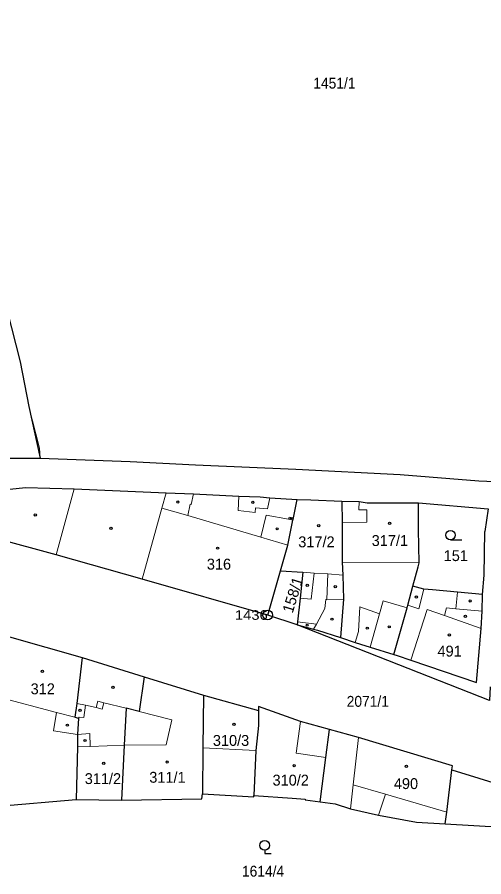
# Model space of a CAD drawing. Extents: x -679733 to -673243, y -1075091 to -1066557.
# Drawn here: x -676925.4 to -676852.3, y -1071438.3 to -1071303.8 of the extents above; entities that cross this region are included whole.
import ezdxf
from ezdxf.enums import TextEntityAlignment as Align

# ---------------------------------------------------------------- set-up
doc = ezdxf.new("R2010")
doc.units = 0
doc.header["$LTSCALE"] = 0.68
for name, color, linetype, lineweight in [('1', 7, 'Continuous', 25), ('3', 7, 'Continuous', 25), ('4', 7, 'Continuous', 13), ('5', 7, 'Continuous', 25), ('8', 7, 'Continuous', 25)]:
    doc.layers.add(name, color=color, linetype=linetype, lineweight=lineweight)
doc.layers.add('2', color=7, linetype='Continuous')

msp = doc.modelspace()

# ---------------------------------------------------------------- linework, layer by layer
at = {"layer": '1'}
for p, q in [((-676886.15, -1071397.33), (-676884.15, -1071390.4)), ((-676896.18, -1071409.85), (-676887.58, -1071412.26)), ((-676916.15, -1071426.2), (-676909.02, -1071426.28))]:
    msp.add_line(p, q, dxfattribs=at)
for points in [[(-676940.16, -1071295.32), (-676934.27, -1071320.03), (-676929.64, -1071339.29), (-676924.89, -1071357.71), (-676923.53, -1071364.72), (-676921.77, -1071372.81)], [(-676946.6, -1071378.41), (-676938.25, -1071374.31), (-676936.51, -1071373.51), (-676931.26, -1071373.06), (-676927.41, -1071372.78), (-676921.77, -1071372.81)], [(-676921.77, -1071372.81), (-676907.7, -1071373.32), (-676897.48, -1071373.81), (-676881.76, -1071374.51), (-676865.44, -1071375.36), (-676853.12, -1071376.35), (-676839.6, -1071376.93), (-676829.31, -1071377.63), (-676824, -1071376.8), (-676807.89, -1071372.89), (-676806.71, -1071372.6)], [(-676926.52, -1071377.66), (-676924.04, -1071377.38), (-676916.45, -1071377.59), (-676902.06, -1071378.22), (-676897.79, -1071378.38), (-676890.67, -1071378.71), (-676887.35, -1071378.83), (-676885.82, -1071378.98), (-676881.52, -1071379.23)], [(-676884.15, -1071390.4), (-676882.99, -1071386.38), (-676882.2, -1071382.48), (-676882.13, -1071382.14), (-676881.52, -1071379.23)], [(-676881.52, -1071379.23), (-676879.42, -1071379.29), (-676874.54, -1071379.53)], [(-676874.54, -1071379.53), (-676874.52, -1071382.83), (-676874.49, -1071389.08), (-676874.37, -1071391.08), (-676874.28, -1071394.86), (-676874.78, -1071400.87)], [(-676874.54, -1071379.53), (-676871.83, -1071379.59), (-676870.57, -1071379.75), (-676862.57, -1071379.75)], [(-676863.46, -1071392.84), (-676862.62, -1071389.77), (-676862.43, -1071389.14), (-676862.53, -1071383.97), (-676862.57, -1071379.75)], [(-676862.57, -1071379.75), (-676851.64, -1071380.72), (-676852.15, -1071384.24)], [(-676886.15, -1071397.33), (-676905.82, -1071391.71), (-676919.25, -1071387.91), (-676928.69, -1071385.35), (-676934.93, -1071383.52)], [(-676852.51, -1071394.1), (-676852.27, -1071391.08), (-676852.15, -1071384.24)], [(-676884.15, -1071390.4), (-676880.65, -1071390.64), (-676881.08, -1071394.68), (-676881.48, -1071398.39), (-676881.53, -1071398.84)], [(-676866.42, -1071403.52), (-676864.34, -1071396.21), (-676864.22, -1071395.79), (-676863.46, -1071392.84)], [(-676852.51, -1071394.1), (-676856.44, -1071393.75), (-676860.36, -1071393.37), (-676861.71, -1071393.27), (-676863.46, -1071392.84)], [(-676949.74, -1071393.86), (-676947.08, -1071394.44), (-676942.33, -1071395.72), (-676930.37, -1071399.53), (-676926.55, -1071400.72), (-676915.2, -1071403.96), (-676905.51, -1071407), (-676896.18, -1071409.85)], [(-676866.42, -1071403.52), (-676865.9, -1071403.66), (-676863.75, -1071404.41), (-676853.5, -1071407.89), (-676852.74, -1071399.45), (-676852.59, -1071396.73), (-676852.51, -1071394.1)], [(-676851.36, -1071408.59), (-676851.44, -1071410.69), (-676881.53, -1071398.84), (-676886.15, -1071397.33)], [(-676881.53, -1071398.84), (-676878.97, -1071399.54), (-676878.36, -1071399.71), (-676874.78, -1071400.87)], [(-676874.78, -1071400.87), (-676872.44, -1071401.63), (-676871.65, -1071401.89), (-676870.12, -1071402.35), (-676866.42, -1071403.52)], [(-676915.2, -1071403.96), (-676916.03, -1071411.16), (-676916.33, -1071413.29), (-676915.75, -1071413.46), (-676915.9, -1071416.04), (-676915.95, -1071417.96), (-676916.15, -1071426.2)], [(-676905.51, -1071407), (-676906.29, -1071412.43), (-676908.32, -1071411.93), (-676908.6, -1071417.71), (-676909.02, -1071426.28)], [(-676896.18, -1071409.85), (-676896.29, -1071418.09), (-676896.38, -1071425.29)], [(-676887.58, -1071412.26), (-676887.62, -1071414.63), (-676888.01, -1071418.55), (-676888.34, -1071425.58)], [(-676876.47, -1071415.25), (-676881, -1071414), (-676887.57, -1071411.66), (-676887.58, -1071412.26)], [(-676877.94, -1071426.56), (-676877.04, -1071419.6), (-676876.47, -1071415.25)], [(-676857.31, -1071421.54), (-676857.23, -1071420.94), (-676871.95, -1071416.49), (-676876.47, -1071415.25)], [(-676928.68, -1071418.83), (-676928.63, -1071420.02), (-676928.57, -1071421.48), (-676928.33, -1071427.24), (-676916.15, -1071426.2)], [(-676858.38, -1071430.03), (-676858.1, -1071428.19), (-676857.31, -1071421.54)], [(-676857.31, -1071421.54), (-676821.49, -1071432.6), (-676813.29, -1071435.89)], [(-676909.02, -1071426.28), (-676896.45, -1071426.09), (-676896.38, -1071425.29)], [(-676896.38, -1071425.29), (-676888.35, -1071425.77), (-676888.34, -1071425.58)], [(-676888.34, -1071425.58), (-676882.32, -1071426.01), (-676880.27, -1071426.12), (-676880.28, -1071426.24), (-676877.94, -1071426.56)], [(-676877.94, -1071426.56), (-676875.62, -1071426.88), (-676873.17, -1071427.67), (-676868.81, -1071428.67), (-676862.89, -1071429.74), (-676858.38, -1071430.03)], [(-676858.38, -1071430.03), (-676839.52, -1071431.11), (-676827.87, -1071433.27), (-676821.49, -1071432.6)]]:
    msp.add_lwpolyline(points, dxfattribs=at)
at = {"layer": '3'}
msp.add_line((-676857.543, -1071385.58), (-676855.793, -1071385.58), dxfattribs=at)
msp.add_lwpolyline([(-676886.63, -1071434.122), (-676886.63, -1071434.62), (-676885.629, -1071434.62)], dxfattribs=at)
for centre in [(-676857.5429, -1071384.8298), (-676886.6293, -1071433.3709)]:
    msp.add_circle(centre, 0.75, dxfattribs=at)
at = {"layer": '4'}
for p, q in [((-676923.53, -1071364.72), (-676921.87, -1071371.22)), ((-676921.77, -1071372.81), (-676921.87, -1071371.22)), ((-676919.25, -1071387.91), (-676916.45, -1071377.59)), ((-676902.73, -1071380.63), (-676902.06, -1071378.22)), ((-676898.15, -1071380.05), (-676897.79, -1071378.38)), ((-676890.76, -1071380.97), (-676890.67, -1071378.71)), ((-676898.68, -1071381.78), (-676898.29, -1071380.01)), ((-676898.29, -1071380.01), (-676898.15, -1071380.05)), ((-676885.82, -1071378.98), (-676886.19, -1071380.69)), ((-676871.88, -1071380.87), (-676871.83, -1071379.59)), ((-676905.82, -1071391.71), (-676902.73, -1071380.63)), ((-676902.73, -1071380.63), (-676898.68, -1071381.78)), ((-676888.14, -1071381.29), (-676890.76, -1071380.97)), ((-676888.05, -1071380.55), (-676888.14, -1071381.29)), ((-676886.19, -1071380.69), (-676888.05, -1071380.55)), ((-676870.64, -1071380.86), (-676871.88, -1071380.87)), ((-676870.65, -1071382.81), (-676870.64, -1071380.86)), ((-676898.68, -1071381.78), (-676887.22, -1071385.14)), ((-676887.22, -1071385.14), (-676886.41, -1071381.69)), ((-676886.41, -1071381.69), (-676882.89, -1071382.35)), ((-676882.82, -1071382.01), (-676882.89, -1071382.35)), ((-676882.89, -1071382.35), (-676882.2, -1071382.48)), ((-676882.13, -1071382.14), (-676882.82, -1071382.01)), ((-676874.52, -1071382.83), (-676870.65, -1071382.81)), ((-676887.22, -1071385.14), (-676882.99, -1071386.38)), ((-676874.49, -1071389.08), (-676862.43, -1071389.14)), ((-676880.65, -1071390.64), (-676878.88, -1071390.77)), ((-676878.88, -1071390.77), (-676879.35, -1071394.87)), ((-676878.88, -1071390.77), (-676876.76, -1071390.91)), ((-676876.76, -1071390.91), (-676876.89, -1071394.89)), ((-676876.76, -1071390.91), (-676874.37, -1071391.08)), ((-676861.71, -1071393.27), (-676862.48, -1071396.34)), ((-676881.08, -1071394.68), (-676879.35, -1071394.87)), ((-676877.07, -1071394.89), (-676877.22, -1071396.3)), ((-676877.07, -1071394.89), (-676876.89, -1071394.89)), ((-676876.89, -1071394.89), (-676874.28, -1071394.86)), ((-676856.71, -1071396.34), (-676856.44, -1071393.75)), ((-676871.93, -1071399.9), (-676871.76, -1071396.04)), ((-676871.76, -1071396.04), (-676868.65, -1071397.13)), ((-676868.07, -1071395.09), (-676868.65, -1071397.13)), ((-676864.34, -1071396.21), (-676868.07, -1071395.09)), ((-676864.22, -1071395.79), (-676862.48, -1071396.34)), ((-676858.47, -1071397.42), (-676858.15, -1071396.2)), ((-676858.15, -1071396.2), (-676856.71, -1071396.34)), ((-676878.54, -1071398.75), (-676877.22, -1071396.3)), ((-676868.65, -1071397.13), (-676870.12, -1071402.35)), ((-676863.75, -1071404.41), (-676861.2, -1071396.46)), ((-676861.2, -1071396.46), (-676858.47, -1071397.42)), ((-676858.47, -1071397.42), (-676852.74, -1071399.45)), ((-676856.71, -1071396.34), (-676852.59, -1071396.73)), ((-676881.48, -1071398.39), (-676878.54, -1071398.75)), ((-676878.97, -1071399.54), (-676878.54, -1071398.75)), ((-676872.44, -1071401.63), (-676871.93, -1071399.9)), ((-676928.28, -1071410.2), (-676919.2, -1071412.56)), ((-676912.74, -1071410.82), (-676913.01, -1071411.79)), ((-676911.78, -1071411.09), (-676912.74, -1071410.82)), ((-676914.66, -1071411.45), (-676916.03, -1071411.16)), ((-676914.66, -1071411.45), (-676914.92, -1071413.39)), ((-676913.01, -1071411.79), (-676914.66, -1071411.45)), ((-676913.01, -1071411.79), (-676912.04, -1071412.05)), ((-676912.04, -1071412.05), (-676911.78, -1071411.09)), ((-676908.32, -1071411.93), (-676911.78, -1071411.09)), ((-676919.67, -1071415.43), (-676919.2, -1071412.56)), ((-676919.2, -1071412.56), (-676916.33, -1071413.29)), ((-676915.65, -1071413.33), (-676915.75, -1071413.46)), ((-676914.92, -1071413.39), (-676915.65, -1071413.33)), ((-676906.29, -1071412.43), (-676901.18, -1071413.75)), ((-676901.18, -1071413.75), (-676902.03, -1071417.63)), ((-676881, -1071414), (-676881.72, -1071418.97)), ((-676915.9, -1071416.04), (-676919.67, -1071415.43)), ((-676915.9, -1071416.04), (-676914.02, -1071415.89)), ((-676914.02, -1071415.89), (-676913.95, -1071417.89)), ((-676913.95, -1071417.89), (-676908.6, -1071417.71)), ((-676902.03, -1071417.63), (-676908.6, -1071417.71)), ((-676871.95, -1071416.49), (-676872.78, -1071423.89)), ((-676915.95, -1071417.96), (-676913.95, -1071417.89)), ((-676896.29, -1071418.09), (-676888.01, -1071418.55)), ((-676881.72, -1071418.97), (-676877.04, -1071419.6)), ((-676873.17, -1071427.67), (-676872.78, -1071423.89)), ((-676872.78, -1071423.89), (-676867.74, -1071425.37)), ((-676867.74, -1071425.37), (-676868.81, -1071428.67)), ((-676867.74, -1071425.37), (-676858.1, -1071428.19))]:
    msp.add_line(p, q, dxfattribs=at)
at = {"layer": '5'}
for centre, radius in [((-676900.2268, -1071379.6592), 0.175), ((-676888.4768, -1071379.7092), 0.175), ((-676922.5268, -1071381.6792), 0.175), ((-676882.5246, -1071382.2394), 0.1172), ((-676867.0668, -1071382.9792), 0.175), ((-676910.6868, -1071383.7592), 0.175), ((-676884.6768, -1071383.8492), 0.175), ((-676878.1768, -1071383.3492), 0.175), ((-676893.9868, -1071386.8692), 0.175), ((-676879.9668, -1071392.6692), 0.175), ((-676875.5868, -1071392.9092), 0.175), ((-676862.8868, -1071394.5192), 0.175), ((-676854.4668, -1071395.1292), 0.175), ((-676855.2168, -1071397.5292), 0.175), ((-676879.9768, -1071398.9192), 0.175), ((-676876.1068, -1071397.9792), 0.175), ((-676870.5768, -1071399.3892), 0.175), ((-676867.1368, -1071399.1792), 0.175), ((-676857.7168, -1071400.4392), 0.175), ((-676921.4268, -1071406.1592), 0.175), ((-676910.3868, -1071408.6392), 0.175), ((-676915.5268, -1071412.2492), 0.175), ((-676917.5068, -1071414.5592), 0.175), ((-676891.4368, -1071414.4392), 0.175), ((-676914.7368, -1071416.9692), 0.175), ((-676911.8268, -1071420.5192), 0.175), ((-676901.8968, -1071420.3392), 0.175), ((-676882.0168, -1071420.9192), 0.175), ((-676864.4568, -1071420.9892), 0.175)]:
    msp.add_circle(centre, radius, dxfattribs=at)
at = {"layer": '8'}
for radius in [0.75, 0.03]:
    msp.add_circle((-676886.15, -1071397.3298), radius, dxfattribs=at)

# ---------------------------------------------------------------- texts
at = {"layer": '2', "width": 0.95}
for s, p in [('1451/1', (-676879.02, -1071314.95)), ('2071/1', (-676873.79, -1071411.69)), ('1614/4', (-676890.18, -1071438.269))]:
    msp.add_text(s, height=1.7, dxfattribs=at).set_placement(p)
at = {"layer": '2'}
for s, p in [('317/2', (-676881.37, -1071386.729)), ('317/1', (-676869.88, -1071386.529)), ('151', (-676858.61, -1071388.89)), ('316', (-676895.68, -1071390.22)), ('491', (-676859.58, -1071403.83)), ('312', (-676923.26, -1071409.729)), ('310/3', (-676894.74, -1071417.81)), ('311/1', (-676904.69, -1071423.57)), ('311/2', (-676914.79, -1071423.779)), ('310/2', (-676885.4, -1071424.019)), ('490', (-676866.41, -1071424.56))]:
    msp.add_text(s, height=1.7, dxfattribs=at).set_placement(p)
msp.add_text('158/1', height=1.7, rotation=73, dxfattribs=at).set_placement((-676882.257, -1071397.148))
at = {"layer": '8', "width": 1.15}
msp.add_text('1436', height=1.5, dxfattribs=at).set_placement((-676886.149, -1071398.08), align=Align.RIGHT)

doc.saveas('drawing.dxf')
